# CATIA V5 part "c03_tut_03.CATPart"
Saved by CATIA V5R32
Part number: c03tut3
Bounding box of the stored display mesh (mm): x 0 to 0, y -100 to 100, z 0 to 90
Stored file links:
  D:\PROJECTS\Project 2022\CATIA V5 6R 2022\Resources\Tutorial Files\c03_catia_v5_6r2021_tut\c03_tut_03.CATPart
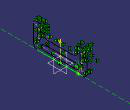
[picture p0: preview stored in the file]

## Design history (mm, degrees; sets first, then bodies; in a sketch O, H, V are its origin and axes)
Body1 (main body)
  Sketch1 on yz-plane, origin (0, 0, 0), H (0, 1, 0), V (0, 0, 1)
    line L1 (0, 0) -> (85, 0)
    line L2 (100, 15) -> (100, 80)
    line L3 (90, 90) -> (70, 90)
    line L4 (60, 80) -> (60, 60)
    line L5 (50, 50) -> (0, 50)
    point P1 (0, 50)
    arc A1 centre (85, 15) radius 15 from (85, 0) to (100, 15) ccw
    point P2 (85, 0)
    point P3 (100, 15)
    arc A2 centre (90, 80) radius 10 from (100, 80) to (90, 90) ccw
    point P5 (100, 80)
    point P6 (90, 90)
    arc A3 centre (70, 80) radius 10 from (70, 90) to (60, 80) ccw
    point P8 (70, 90)
    point P9 (60, 80)
    arc A4 centre (50, 60) radius 10 from (60, 60) to (50, 50) cw
    point P11 (60, 60)
    point P12 (50, 50)
    construction line L6 (80, 40) -> (80, 70)
    line L7 (75, 40) -> (75, 70)
    line L8 (85, 70) -> (85, 40)
    arc A5 centre (80, 70) radius 5 from (75, 70) to (85, 70) cw
    arc A6 centre (80, 40) radius 5 from (85, 40) to (75, 40) cw
    point P16 (75, 40)
    point P17 (75, 70)
    point P18 (85, 70)
    point P19 (85, 40)
    point P20 (0, 0)
    construction line L9 through (0, 0) direction (-1, 0)
    point P21 (0, 50)
    point P22 (-85, 0)
    point P23 (-100, 15)
    point P25 (-100, 80)
    point P26 (-90, 90)
    point P28 (-70, 90)
    point P29 (-60, 80)
    point P31 (-60, 60)
    point P32 (-50, 50)
    construction line L10 (-80, 40) -> (-80, 70)
    point P36 (-75, 40)
    point P37 (-75, 70)
    point P38 (-85, 70)
    point P39 (-85, 40)
    line L11 (-100, 15) -> (-100, 80)
    line L12 (-90, 90) -> (-70, 90)
    line L13 (-60, 80) -> (-60, 60)
    line L14 (-50, 50) -> (0, 50)
    arc A7 centre (-85, 15) radius 15 from (-85, 0) to (-100, 15) cw
    arc A8 centre (-90, 80) radius 10 from (-100, 80) to (-90, 90) cw
    arc A9 centre (-70, 80) radius 10 from (-70, 90) to (-60, 80) cw
    arc A10 centre (-50, 60) radius 10 from (-60, 60) to (-50, 50) ccw
    line L15 (-75, 40) -> (-75, 70)
    line L16 (-85, 70) -> (-85, 40)
    arc A11 centre (-80, 70) radius 5 from (-75, 70) to (-85, 70) ccw
    arc A12 centre (-80, 40) radius 5 from (-85, 40) to (-75, 40) ccw
    line L17 (0, 0) -> (-85, 0)
    construction line L18 (60, 20) -> (-60, 20)
    point P40 (-60, 20)
    line L19 (60, 10) -> (-60, 10)
    line L20 (-60, 30) -> (60, 30)
    arc A13 centre (-60, 20) radius 10 from (-60, 10) to (-60, 30) cw
    arc A14 centre (60, 20) radius 10 from (60, 30) to (60, 10) cw
    radius A1 = 15
    radius A2 = 10
    radius A3 = 10
    radius A4 = 10
    distance L6 L7 = 5
    distance L18 L19 = 10
    horizontal: L1 H, L3 H, L5 H, L18 H
    vertical: L2 V, L4 V, L6 V
    tangency: A1 L1, A1 L2, A2 L2, A2 L3, A3 L3, A3 L4, A4 L4, A4 L5, A5 L7, A6 L7, A5 L8, A6 L8, A13 L19, A14 L19, A13 L20, A14 L20
    symmetry: O P20 V, H L9 V, P1 P21 V, P2 P22 V, P3 P23 V, P5 P25 V, P6 P26 V, P8 P28 V, P9 P29 V, P11 P31 V, P12 P32 V, L6 L10 V, P16 P36 V, P17 P37 V, P18 P38 V, P19 P39 V, L2 L11 V, L3 L12 V, L4 L13 V, L5 L14 V, A1 A7 V, A2 A8 V, A3 A9 V, A4 A10 V, L7 L15 V, L8 L16 V, A5 A11 V, A6 A12 V, L1 L17 V
    coincidence: P40 L13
